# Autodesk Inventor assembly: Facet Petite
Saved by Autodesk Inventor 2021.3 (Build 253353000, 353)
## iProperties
Created: 2022-09
Part Number: Facet Petite
Document SubType Name: Assembly
Designer: Administrator
Title: Facet Petite v6
Author: Administrator
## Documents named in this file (3)
- c:\worker\convert-fusion-r05\tmp\job-1\179\output\files\606792e5-a35f-4ee1-951f-0ce7651e4afc\eca62228-0d37-4c8e-b826-1c013af9a457.iam
- c:\worker\convert-fusion-r05\tmp\job-1\179\output\files\606792e5-a35f-4ee1-951f-0ce7651e4afc\Facet Petite.ipt
- c:\worker\convert-fusion-r05\tmp\job-1\179\output\files\606792e5-a35f-4ee1-951f-0ce7651e4afc\Part4.ipt
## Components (2 placed, 2 different names)
1. Facet Petite:1
2. Part4
